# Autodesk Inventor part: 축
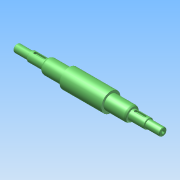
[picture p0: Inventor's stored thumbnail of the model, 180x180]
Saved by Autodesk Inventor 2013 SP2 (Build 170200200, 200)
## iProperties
Created: 2025-10
Part Number: 축
Material: Generic
Document SubType Name: Modeling
Designer: 601
Density: 1 g/cm^3
Author: 601
변환 표준: STEP AP214IS
전처리기: Build: 200, Release: 2013 SP2 Update 6 - Date: Thu 07/17/2014
전송 단위: 밀리미터
불확실성: 0.01
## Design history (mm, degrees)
node "축1"
node "솔리드1"
node "기준1"
